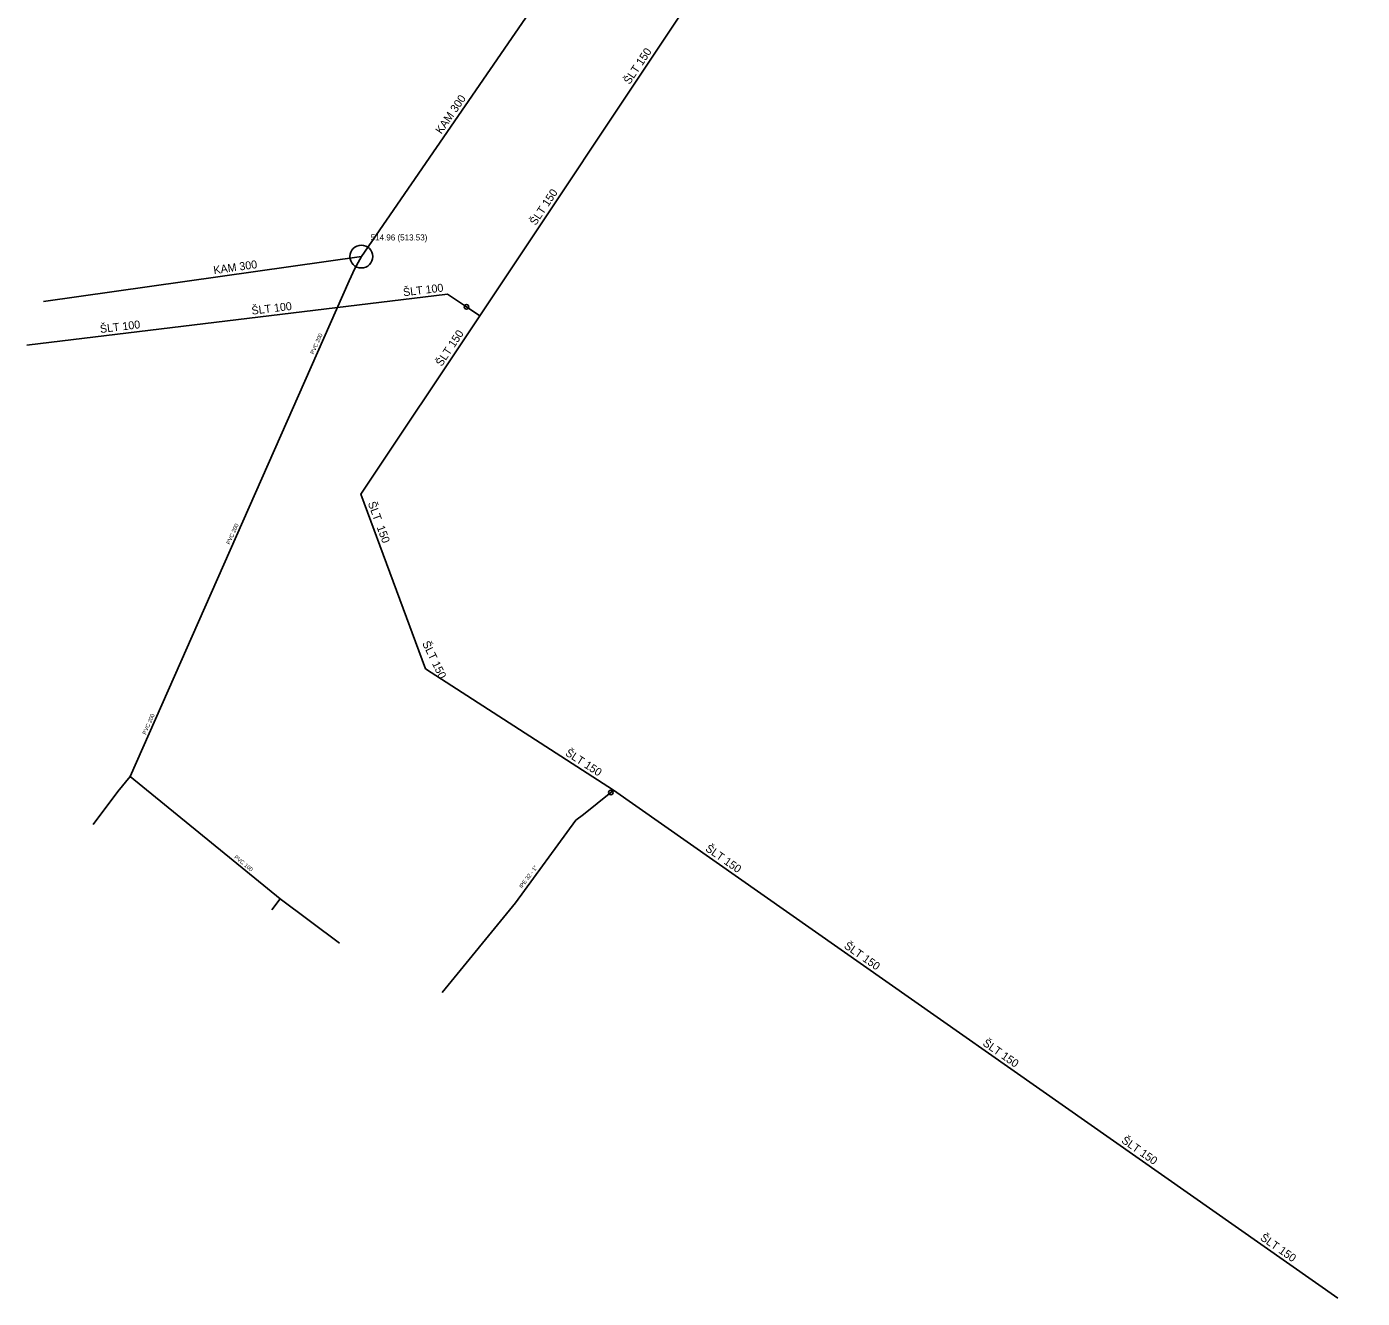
# Model space of a CAD drawing. Extents: x -668995 to -668929, y -1128059 to -1127935.
# Drawn here: x -668995.4 to -668966.11, y -1128059.49 to -1128031.61 of the extents above; entities that cross this region are included whole.
import ezdxf

# ---------------------------------------------------------------- set-up
doc = ezdxf.new("R2010")
doc.units = 0
for name, color, linetype in [('Implicitní', 7, 'Continuous'), ('JEDN', 7, 'Continuous'), ('JEDN_D', 7, 'Continuous'), ('k_sachta_clip_Layer', 7, 'Continuous'), ('k_sachta_clip_LayerAnotace', 7, 'Continuous'), ('k_sachta_o', 7, 'Continuous'), ('kanal_clip_LayerAnotace', 7, 'Continuous'), ('soupe_o', 7, 'Continuous'), ('VOD', 7, 'Continuous'), ('VOD_O', 7, 'Continuous'), ('vodovod_clip_LayerAnotace', 7, 'Continuous')]:
    doc.layers.add(name, color=color, linetype=linetype)

msp = doc.modelspace()

# ---------------------------------------------------------------- linework, layer by layer
at = {"layer": 'JEDN'}
msp.add_line((-668990.02, -1128050.97), (-668989.842, -1128050.729), dxfattribs=at)
for points in [[(-668993.944, -1128049.105), (-668993.4, -1128048.38), (-668993.13, -1128048.05), (-668988.33, -1128037.18), (-668988.2, -1128036.91), (-668988.06, -1128036.65)], [(-668988.543, -1128051.701), (-668989.842, -1128050.729), (-668993.13, -1128048.05)]]:
    msp.add_lwpolyline(points, dxfattribs=at)
at = {"layer": 'JEDN_D'}
for p, q in [((-668988.06, -1128036.65), (-668966.11, -1128004.77)), ((-668995.027, -1128037.637), (-668988.06, -1128036.65))]:
    msp.add_line(p, q, dxfattribs=at)
at = {"layer": 'k_sachta_clip_Layer'}
msp.add_line((-668988.06, -1128036.65), (-668988.06, -1128036.65), dxfattribs=at)
at = {"layer": 'k_sachta_o'}
msp.add_circle((-668988.06, -1128036.65), 0.25, dxfattribs=at)
at = {"layer": 'soupe_o'}
for centre in [(-668985.754, -1128037.753), (-668982.59, -1128048.4)]:
    msp.add_circle(centre, 0.05, dxfattribs=at)
at = {"layer": 'VOD'}
msp.add_lwpolyline([(-668986.286, -1128052.787), (-668984.68, -1128050.82), (-668983.36, -1128049.01), (-668983.19, -1128048.88), (-668982.59, -1128048.4), (-668982.53, -1128048.35)], dxfattribs=at)
at = {"layer": 'VOD_O'}
for points in [[(-668980.925, -1128031.139), (-668985.463, -1128037.947), (-668988.07, -1128041.858), (-668986.656, -1128045.686), (-668982.53, -1128048.35), (-668966.644, -1128059.489)], [(-668985.463, -1128037.947), (-668985.754, -1128037.753), (-668986.17, -1128037.476), (-668995.399, -1128038.594)]]:
    msp.add_lwpolyline(points, dxfattribs=at)

# ---------------------------------------------------------------- texts
at = {"layer": 'Implicitní'}
msp.add_text('ŠLT  150', height=0.1755, rotation=290.2733, dxfattribs=at).set_placement((-668987.921, -1128042.057))
at = {"layer": 'k_sachta_clip_LayerAnotace'}
msp.add_text('514.96 (513.53)', height=0.13163, dxfattribs=at).set_placement((-668987.855, -1128036.297))
at = {"layer": 'kanal_clip_LayerAnotace'}
for s, height, rotation, p in [('KAM 300', 0.1755, 55.4519, (-668986.305, -1128033.977)), ('KAM 300', 0.1755, 8.0676, (-668991.291, -1128037.037)), ('PVC 200', 0.0878, 66.1745, (-668989.104, -1128038.802)), ('PVC 200', 0.0878, 66.1746, (-668990.945, -1128042.971)), ('PVC 200', 0.0878, 66.1746, (-668992.786, -1128047.14)), ('PVC 100', 0.0878, 320.8275, (-668990.858, -1128049.833))]:
    msp.add_text(s, height=height, rotation=rotation, dxfattribs=at).set_placement(p)
at = {"layer": 'vodovod_clip_LayerAnotace'}
for s, height, rotation, p in [('ŠLT 150', 0.1755, 56.3136, (-668982.177, -1128032.89)), ('ŠLT 150', 0.1755, 56.3137, (-668984.237, -1128035.981)), ('ŠLT 100', 0.1755, 6.9098, (-668987.134, -1128037.522)), ('ŠLT 100', 0.1755, 6.9098, (-668990.458, -1128037.925)), ('ŠLT 100', 0.1755, 6.9097, (-668993.782, -1128038.327)), ('ŠLT 150', 0.1755, 56.3136, (-668986.298, -1128039.072)), ('ŠLT 150', 0.1755, 295.8719, (-668986.732, -1128045.128)), ('ŠLT 150', 0.1755, 327.1512, (-668983.604, -1128047.573)), ('ŠLT 150', 0.1755, 324.9612, (-668980.532, -1128049.665)), ('lPE 32 - 1"', 0.08776, 53.236, (-668984.537, -1128050.506)), ('ŠLT 150', 0.1755, 324.9611, (-668977.49, -1128051.798)), ('ŠLT 150', 0.1755, 324.9611, (-668974.449, -1128053.931)), ('ŠLT 150', 0.1755, 324.9612, (-668971.407, -1128056.063)), ('ŠLT 150', 0.1755, 324.9611, (-668968.365, -1128058.196))]:
    msp.add_text(s, height=height, rotation=rotation, dxfattribs=at).set_placement(p)

doc.saveas('drawing.dxf')
